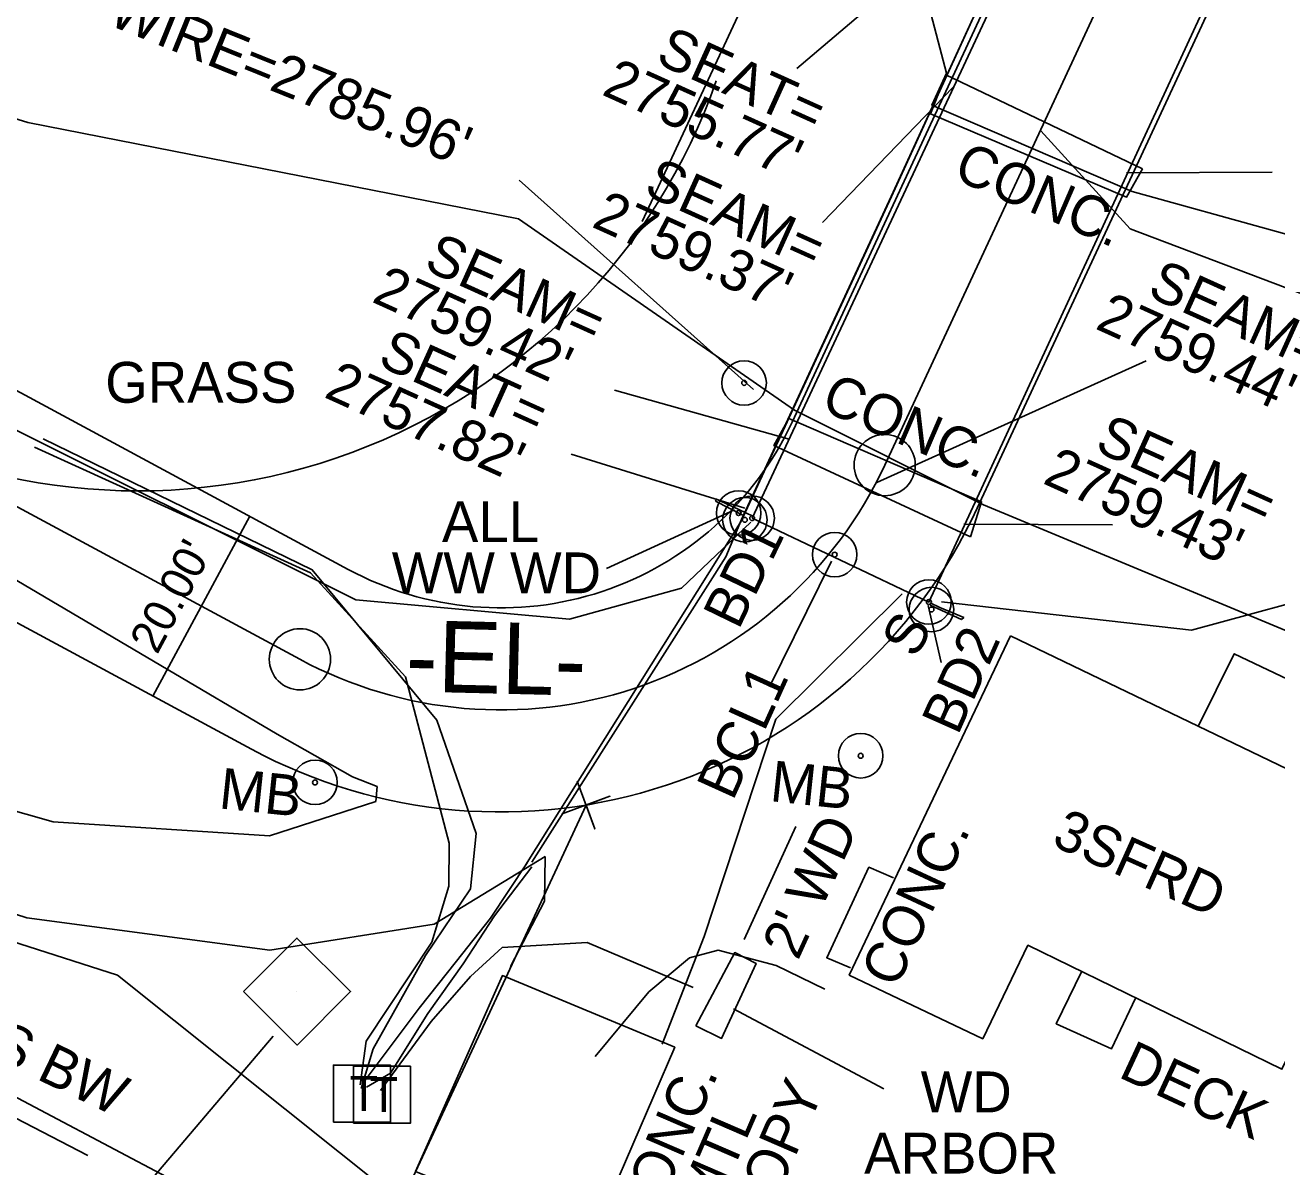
# Model space of a CAD drawing. Extents: x 1271070 to 1271913, y 1027587 to 1028435.
# Drawn here: x 1271502.6 to 1271625.3, y 1028044 to 1028155.9 of the extents above; entities that cross this region are included whole.
import ezdxf

# ---------------------------------------------------------------- set-up
doc = ezdxf.new("R2010")
doc.units = 0
for name, color, linetype in [('CTL Secondary Horizontal and Vertical CELL', 7, 'Continuous'), ('CTL Secondary Horizontal and Vertical Leader', 7, 'Continuous'), ('Exist Building', 7, 'Continuous'), ('Exist Building Text', 7, 'Continuous'), ('Exist Horizontal Alignment', 7, 'Continuous'), ('Exist Horizontal Alignment Direction Label', 7, 'Continuous'), ('Exist Horizontal Alignment Point', 7, 'Continuous'), ('Exist Hydro Jurisdictional Stream or Body of Water', 7, 'Continuous'), ('Exist Other Culture Area Outline', 7, 'Continuous'), ('Exist Other Culture Area Outline Leader', 7, 'Continuous'), ('Exist Other Culture Area Outline Text', 7, 'Continuous'), ('Exist Other Culture Fence Line', 7, 'Continuous'), ('Exist Other Culture Fence Line Text', 7, 'Continuous'), ('Exist Other Culture Located Object CELL', 7, 'Continuous'), ('Exist Other Culture Located Object Leader', 7, 'Continuous'), ('Exist Other Culture Located Object Text', 7, 'Continuous'), ('Exist Other Culture Sign CELL', 7, 'Continuous'), ('Exist Other Culture Sign Text', 7, 'Continuous'), ('Exist Property Corner CELL', 7, 'Continuous'), ('Exist Property Line', 7, 'Continuous'), ('Exist Right of Way Line', 7, 'Continuous'), ('Exist Right of Way Width CELL', 7, 'Continuous'), ('Exist Roads EOP Other', 7, 'Continuous'), ('Exist Roads EOP Other Text', 7, 'Continuous'), ('Exist Roads Soil', 7, 'Continuous'), ('Exist Structure Major Bridge WW', 7, 'Continuous'), ('Exist Structure Major Bridge WW Leader', 7, 'Continuous'), ('Exist Structure Major Bridge WW Text', 7, 'Continuous'), ('Exist Structure Major Deck Tunnel Box Culvert', 7, 'Continuous'), ('Exist Utilities Other Located Object CELL', 7, 'Continuous'), ('Exist Utilities Other Located Object Leader', 7, 'Continuous'), ('Exist Utilities Other Located Object Text', 7, 'Continuous'), ('Exist Utilities Power UG Cable SUE LOS C', 7, 'Continuous'), ('Exist Utilities Telephone Pedestal CELL', 7, 'Continuous'), ('Exist Utilities Telephone UG Cable SUE LOS C', 7, 'Continuous'), ('Exist Vegetation Woods Line', 7, 'Continuous'), ('Exist Vegetation Woods Line Text', 7, 'Continuous'), ('Prop Horizontal Alignment', 7, 'Continuous')]:
    doc.layers.add(name, color=color, linetype=linetype)

msp = doc.modelspace()

# ---------------------------------------------------------------- linework, layer by layer
at = {"layer": 'CTL Secondary Horizontal and Vertical CELL'}
msp.add_line((1271529.25, 1028061.16), (1271529.25, 1028061.16), dxfattribs=at)
msp.add_lwpolyline([(1271524.03, 1028061.18), (1271529.27, 1028066.42), (1271534.52, 1028061.17), (1271529.28, 1028055.93)], close=True, dxfattribs=at)
at = {"layer": 'CTL Secondary Horizontal and Vertical Leader'}
msp.add_line((1271526.93, 1028056.81), (1271502.68, 1028028.26), dxfattribs=at)
at = {"layer": 'Exist Building'}
msp.add_lwpolyline([(1271599.17, 1028096.03), (1271637.63, 1028077.51), (1271625.75, 1028053.57), (1271600.86, 1028065.71), (1271596.44, 1028056.55), (1271583.36, 1028062.79), (1271599.17, 1028096.03)], dxfattribs=at)
at = {"layer": 'Exist Horizontal Alignment'}
for p, q in [((1271563.09, 1028136.63), (1271612.17, 1028242.18)), ((1271586.84, 1028112.76), (1271635.92, 1028218.31)), ((1271497.89, 1028110.8), (1271529.56, 1028093.74))]:
    msp.add_line(p, q, dxfattribs=at)
msp.add_arc((1271549.23, 1028130.25), 41.48, 241.6832, 335.0649, dxfattribs=at)
at = {"layer": 'Exist Horizontal Alignment Point'}
for centre in [(1271586.84, 1028112.76), (1271529.56, 1028093.73)]:
    msp.add_circle(centre, 3, dxfattribs=at)
at = {"layer": 'Exist Hydro Jurisdictional Stream or Body of Water'}
for points in [[(1271304.7, 1028214.03), (1271358.66, 1028206.9), (1271411.07, 1028198.58), (1271456, 1028198.43), (1271510.08, 1028186.94), (1271560.93, 1028171.69), (1271591.08, 1028158.12), (1271592.88, 1028151.16), (1271591.46, 1028148.01), (1271611.09, 1028139.56), (1271653.5, 1028127.81), (1271692.8, 1028106.61), (1271731.61, 1028109.95), (1271774.25, 1028123.55), (1271810.26, 1028145.38)], [(1271297.21, 1028193.87), (1271353.83, 1028172.03), (1271400.51, 1028161.95), (1271458.18, 1028160.15), (1271502.92, 1028146.33), (1271550.98, 1028136.88), (1271578, 1028118.14), (1271596.52, 1028108.85), (1271635.13, 1028092.8), (1271673.17, 1028073.83), (1271694.14, 1028069.18), (1271732.54, 1028081.77), (1271795.86, 1028101.38), (1271818.57, 1028109)]]:
    msp.add_lwpolyline(points, dxfattribs=at)
at = {"layer": 'Exist Other Culture Area Outline'}
for points in [[(1271617.56, 1028087.16), (1271621.08, 1028094.27), (1271640.79, 1028084.89), (1271647.27, 1028072.76), (1271658.66, 1028067.57), (1271647.71, 1028044.28), (1271626.25, 1028054.12)], [(1271568.33, 1028057.81), (1271572.15, 1028065), (1271574.24, 1028063.94), (1271570.86, 1028056.58), (1271568.33, 1028057.81)], [(1271606.13, 1028063.1), (1271603.65, 1028058.02), (1271609.04, 1028055.56), (1271611.4, 1028060.53)]]:
    msp.add_lwpolyline(points, dxfattribs=at)
at = {"layer": 'Exist Other Culture Area Outline Leader'}
msp.add_line((1271572.04, 1028059.5), (1271586.75, 1028051.65), dxfattribs=at)
at = {"layer": 'Exist Other Culture Fence Line'}
msp.add_line((1271578.12, 1028077.36), (1271573.06, 1028066.28), dxfattribs=at)
for points in [[(1271580.99, 1028013.16), (1271535.55, 1028032.92), (1271492.32, 1028055.79), (1271450.78, 1028076.46)], [(1271473.41, 1028044.33), (1271471.4, 1028064.49), (1271508.77, 1028045.12)]]:
    msp.add_lwpolyline(points, dxfattribs=at)
at = {"layer": 'Exist Other Culture Located Object CELL'}
for centre, radius in [((1271573.86, 1028107.56), 2.18), ((1271573.86, 1028107.56), 0.24), ((1271581.94, 1028103.99), 2.18), ((1271581.94, 1028103.99), 0.24), ((1271591.17, 1028099.34), 2.18), ((1271591.17, 1028099.34), 0.24), ((1271584.49, 1028084.28), 2.18), ((1271584.49, 1028084.28), 0.24), ((1271531.04, 1028081.67), 2.18), ((1271531.04, 1028081.67), 0.24)]:
    msp.add_circle(centre, radius, dxfattribs=at)
at = {"layer": 'Exist Other Culture Located Object Leader'}
for p, q in [((1271593.55, 1028149.78), (1271580.76, 1028136.54)), ((1271610.51, 1028141.39), (1271624.79, 1028141.45)), ((1271586.06, 1028111.05), (1271612.45, 1028122.99)), ((1271577.48, 1028115.31), (1271560.37, 1028120.11)), ((1271581.62, 1028103.36), (1271575.56, 1028091.05)), ((1271591.11, 1028099.01), (1271592.38, 1028093.43))]:
    msp.add_line(p, q, dxfattribs=at)
for points in [[(1271602.98, 1028172.65), (1271578.23, 1028151.61)], [(1271602.13, 1028145.52), (1271610.87, 1028135.91), (1271635.48, 1028126.6)], [(1271573.13, 1028108.54), (1271556.14, 1028113.84)], [(1271594.59, 1028106.98), (1271609.16, 1028106.91)], [(1271592.41, 1028099.36), (1271616.88, 1028096.6), (1271632.26, 1028100.77)]]:
    msp.add_lwpolyline(points, dxfattribs=at)
at = {"layer": 'Exist Other Culture Sign CELL'}
for centre, radius in [((1271572.53, 1028108.06), 2.18), ((1271573.14, 1028107.4), 2.18), ((1271572.53, 1028108.06), 0.24), ((1271573.14, 1028107.4), 0.24), ((1271591.42, 1028098.61), 2.18), ((1271591.42, 1028098.61), 0.24)]:
    msp.add_circle(centre, radius, dxfattribs=at)
at = {"layer": 'Exist Property Corner CELL'}
msp.add_line((1271557.59, 1028079.45), (1271557.59, 1028079.45), dxfattribs=at)
msp.add_lwpolyline([(1271556.73, 1028081.8), (1271558.44, 1028077.11), (1271557.59, 1028079.45), (1271559.93, 1028080.31), (1271555.24, 1028078.6)], dxfattribs=at)
at = {"layer": 'Exist Property Line'}
msp.add_line((1271535.79, 1028032.59), (1271557.59, 1028079.45), dxfattribs=at)
at = {"layer": 'Exist Right of Way Line'}
for p, q in [((1271577.77, 1028116.98), (1271616.68, 1028200.67)), ((1271595.91, 1028108.55), (1271637.48, 1028197.96)), ((1271502.63, 1028119.6), (1271534.3, 1028102.54)), ((1271493.15, 1028101.99), (1271524.81, 1028084.93))]:
    msp.add_line(p, q, dxfattribs=at)
for centre, radius, start, end in [((1271355.59, 1027846.7), 310, 61.6832, 80.3766), ((1271549.23, 1028130.25), 31.48, 241.6832, 335.0649), ((1271549.23, 1028130.25), 51.48, 241.6832, 335.0649)]:
    msp.add_arc(centre, radius, start, end, dxfattribs=at)
at = {"layer": 'Exist Right of Way Width CELL'}
for p in [(1271524.65, 1028107.74), (1271515.16, 1028090.13)]:
    msp.add_line(p, (1271520.3, 1028099.68), dxfattribs=at)
at = {"layer": 'Exist Roads EOP Other'}
for points in [[(1271612.09, 1028141.78), (1271592.83, 1028151.01), (1271591.32, 1028147.19), (1271610.54, 1028139.01), (1271612.09, 1028141.78)], [(1271595.24, 1028105.72), (1271575.98, 1028114.67), (1271577.46, 1028117.34), (1271596.33, 1028109.17), (1271595.24, 1028105.72)], [(1271587.71, 1028072.31), (1271585.29, 1028073.35), (1271581.17, 1028064.49), (1271583.49, 1028063.51)], [(1271558.04, 1028036.66), (1271566.28, 1028055.72), (1271549.4, 1028062.75), (1271540.87, 1028043.55), (1271558.04, 1028036.66)]]:
    msp.add_lwpolyline(points, dxfattribs=at)
at = {"layer": 'Exist Roads Soil'}
for points in [[(1271396.41, 1028149.48), (1271447.23, 1028138.55), (1271497.02, 1028118.54), (1271535.05, 1028099.55), (1271555.95, 1028097.65), (1271566.94, 1028100.69), (1271573.74, 1028107.16)], [(1271394.68, 1028139.2), (1271443.87, 1028127.22), (1271493.11, 1028106.58), (1271527.33, 1028086.39), (1271534.7, 1028082.23), (1271537.12, 1028081.26), (1271536.99, 1028079.81), (1271526.58, 1028076.45), (1271505.38, 1028077.81), (1271483.98, 1028083.87), (1271437.08, 1028098.01), (1271387.72, 1028106.24)], [(1271588.56, 1028100.13), (1271576.16, 1028087.86)], [(1271553.57, 1028074.4), (1271542.71, 1028067.79), (1271526.6, 1028065.24), (1271502.81, 1028068.41), (1271480.79, 1028075.51), (1271435.71, 1028089.18), (1271386.06, 1028098.42)], [(1271576.16, 1028087.86), (1271569.14, 1028066.58), (1271565.03, 1028056.02)], [(1271550.17, 1028063.64), (1271553.52, 1028070.04), (1271553.57, 1028074.4)]]:
    msp.add_lwpolyline(points, dxfattribs=at)
at = {"layer": 'Exist Structure Major Bridge WW'}
for p, q in [((1271570.27, 1028109.23), (1271572.94, 1028107.85)), ((1271591.29, 1028099.02), (1271594.35, 1028097.63))]:
    msp.add_line(p, q, dxfattribs=at)
for points in [[(1271570.27, 1028109.23), (1271570.37, 1028109.43), (1271572.54, 1028108.42), (1271573.92, 1028107.74)], [(1271591.3, 1028099.27), (1271592.23, 1028098.82), (1271594.58, 1028097.83), (1271594.35, 1028097.63)]]:
    msp.add_lwpolyline(points, dxfattribs=at)
at = {"layer": 'Exist Structure Major Bridge WW Leader'}
msp.add_line((1271572.12, 1028108.37), (1271559.58, 1028102.63), dxfattribs=at)
at = {"layer": 'Exist Structure Major Deck Tunnel Box Culvert'}
msp.add_lwpolyline([(1271573.86, 1028107.56), (1271604.18, 1028172.48), (1271621.19, 1028164.22), (1271591.17, 1028099.34), (1271573.86, 1028107.56)], dxfattribs=at)
at = {"layer": 'Exist Utilities Other Located Object CELL'}
for radius in [2.18, 0.24]:
    msp.add_circle((1271573.07, 1028120.81), radius, dxfattribs=at)
at = {"layer": 'Exist Utilities Other Located Object Leader'}
msp.add_lwpolyline([(1271573.99, 1028120.18), (1271551.03, 1028140.66)], dxfattribs=at)
at = {"layer": 'Exist Utilities Power UG Cable SUE LOS C'}
msp.add_lwpolyline([(1271580.97, 1028061.4), (1271576.21, 1028063.74), (1271570.54, 1028065.23), (1271567.73, 1028064.48), (1271563.74, 1028061.14), (1271558.48, 1028054.8)], dxfattribs=at)
at = {"layer": 'Exist Utilities Telephone Pedestal CELL'}
for p, q in [((1271535.56, 1028051.21), (1271535.56, 1028051.21)), ((1271537.52, 1028051.1), (1271537.52, 1028051.1))]:
    msp.add_line(p, q, dxfattribs=at)
for points in [[(1271532.84, 1028048.38), (1271538.43, 1028048.38), (1271538.43, 1028053.97), (1271532.84, 1028053.97), (1271532.84, 1028048.38)], [(1271534.8, 1028048.27), (1271540.39, 1028048.27), (1271540.39, 1028053.86), (1271534.8, 1028053.86), (1271534.8, 1028048.27)]]:
    msp.add_lwpolyline(points, dxfattribs=at)
at = {"layer": 'Exist Utilities Telephone UG Cable SUE LOS C'}
for points in [[(1271604.59, 1028190.07), (1271605.13, 1028182.66), (1271604.35, 1028178.41), (1271603.81, 1028174.75), (1271587.49, 1028139.09), (1271572.77, 1028107.28), (1271570.73, 1028103.97), (1271551.65, 1028073.57)], [(1271602.19, 1028190.37), (1271603.06, 1028183.53), (1271604.53, 1028175.31), (1271603.71, 1028174.47), (1271587.48, 1028139.09), (1271572.81, 1028107.42), (1271571.29, 1028103.78), (1271552.27, 1028073.84)], [(1271535.57, 1028051.69), (1271536.73, 1028055.56), (1271541.85, 1028064.7), (1271546.27, 1028071.23), (1271546.83, 1028076.68), (1271542.96, 1028087.76), (1271530.76, 1028102.5), (1271504.41, 1028115.32)], [(1271503.57, 1028114.53), (1271530.61, 1028102.2), (1271539.89, 1028092.01), (1271544.17, 1028075.73), (1271544.13, 1028071.5), (1271542.48, 1028066.01), (1271536.06, 1028056.33), (1271535.47, 1028052.03)], [(1271535.65, 1028052.12), (1271541.25, 1028059.54), (1271544.9, 1028064.14), (1271548.24, 1028068.38), (1271551.81, 1028073.78)], [(1271552.26, 1028073.41), (1271548.63, 1028068.59), (1271545.56, 1028063.88), (1271542.09, 1028059.02), (1271538.43, 1028053.17), (1271536.08, 1028051.8)], [(1271537.46, 1028051.5), (1271542.42, 1028058.25), (1271546.28, 1028062.65), (1271549.37, 1028065.51), (1271557.7, 1028065.97), (1271568.08, 1028061.59)]]:
    msp.add_lwpolyline(points, dxfattribs=at)
at = {"layer": 'Exist Vegetation Woods Line'}
msp.add_lwpolyline([(1271419.54, 1028077.42), (1271428.02, 1028085.14), (1271461.18, 1028078.97), (1271511.68, 1028062.77), (1271549.84, 1028032.3), (1271603.43, 1028018.41), (1271647.71, 1028044.28), (1271672.05, 1028067.4), (1271748.76, 1028084.37), (1271798.88, 1028091.69)], dxfattribs=at)
at = {"layer": 'Prop Horizontal Alignment'}
msp.add_arc((1271513.72, 1028170.23), 60, 240.1367, 340.6957, dxfattribs=at)

# ---------------------------------------------------------------- texts
at = {"layer": 'Exist Building Text'}
msp.add_text('3SFRD', height=4, rotation=335.761, dxfattribs=at).set_placement((1271603.05, 1028075.57))
at = {"layer": 'Exist Horizontal Alignment Direction Label'}
msp.add_text('-EL-', height=7, rotation=358.6064, dxfattribs=at).set_placement((1271539.87, 1028090.59))
at = {"layer": 'Exist Other Culture Area Outline Text'}
msp.add_text('DECK', height=4, rotation=335.0837, dxfattribs=at).set_placement((1271609.61, 1028052.85))
for s, p in [('WD', (1271590.37, 1028049.35)), ('ARBOR', (1271584.83, 1028043.35))]:
    msp.add_text(s, height=4, dxfattribs=at).set_placement(p)
at = {"layer": 'Exist Other Culture Fence Line Text'}
for s, rotation, p in [("2' WD", 65.4588, (1271578.34, 1028064.14)), ('3S BW', 334.3271, (1271496.41, 1028056.14))]:
    msp.add_text(s, height=4, rotation=rotation, dxfattribs=at).set_placement(p)
at = {"layer": 'Exist Other Culture Located Object Text'}
for s, rotation, p in [('SEAT=', 335.6702, (1271564.26, 1028152.22)), ("2755.77'", 335.6702, (1271559.01, 1028149.1)), ('SEAM=', 335.6702, (1271563.1, 1028139.35)), ("2759.37'", 335.6702, (1271558.02, 1028136.15)), ('SEAM=', 335.6702, (1271541.56, 1028132)), ("2759.42'", 335.6702, (1271536.48, 1028128.8)), ('SEAM=', 335.6702, (1271612.43, 1028129.37)), ("2759.44'", 335.6702, (1271607.35, 1028126.17)), ('SEAT=', 335.6702, (1271537.04, 1028122.59)), ("2757.82'", 335.6702, (1271531.8, 1028119.46)), ('SEAM=', 335.6702, (1271607.28, 1028114.22)), ("2759.43'", 335.6702, (1271602.2, 1028111.02)), ('BD1', 64.1022, (1271572.52, 1028096.53)), ('BD2', 65.9983, (1271594, 1028086.19)), ('BCL1', 65.6702, (1271571.96, 1028079.77)), ('MB', 353.9483, (1271521.53, 1028079.14)), ('MB', 353.9483, (1271575.51, 1028079.85))]:
    msp.add_text(s, height=4, rotation=rotation, dxfattribs=at).set_placement(p)
at = {"layer": 'Exist Other Culture Sign Text'}
msp.add_text('S', height=4, rotation=61.4299, dxfattribs=at).set_placement((1271589.87, 1028093.71))
at = {"layer": 'Exist Right of Way Width CELL'}
msp.add_text("20.00'", height=3.2, rotation=61.6832, dxfattribs=at).set_placement((1271515.57, 1028094.11))
at = {"layer": 'Exist Roads EOP Other Text'}
for s, rotation, p in [('CONC.', 336.6101, (1271593.4, 1028140.88)), ('CONC.', 336.6101, (1271580.42, 1028118.23)), ('CONC.', 65.0446, (1271588, 1028061.39)), ('CONC.', 66.6069, (1271563.75, 1028037.35)), ('CANOPY', 66.6069, (1271571.91, 1028030.68)), ('W/ MTL', 66.6069, (1271566.97, 1028032.03))]:
    msp.add_text(s, height=4, rotation=rotation, dxfattribs=at).set_placement(p)
at = {"layer": 'Exist Structure Major Bridge WW Text'}
for s, p in [('ALL', (1271543.47, 1028105.21)), ('WW WD', (1271538.56, 1028100.2))]:
    msp.add_text(s, height=4, dxfattribs=at).set_placement(p)
at = {"layer": 'Exist Utilities Other Located Object Text'}
msp.add_text("LOW WIRE=2785.96'", height=4, rotation=337.9808, dxfattribs=at).set_placement((1271497.9, 1028161.11))
at = {"layer": 'Exist Utilities Telephone Pedestal CELL'}
for p in [(1271534.43, 1028049.49), (1271536.39, 1028049.38)]:
    msp.add_text('T', height=3.42, dxfattribs=at).set_placement(p)
at = {"layer": 'Exist Vegetation Woods Line Text'}
msp.add_text('GRASS', height=4, dxfattribs=at).set_placement((1271510.49, 1028118.87))

doc.saveas('drawing.dxf')
